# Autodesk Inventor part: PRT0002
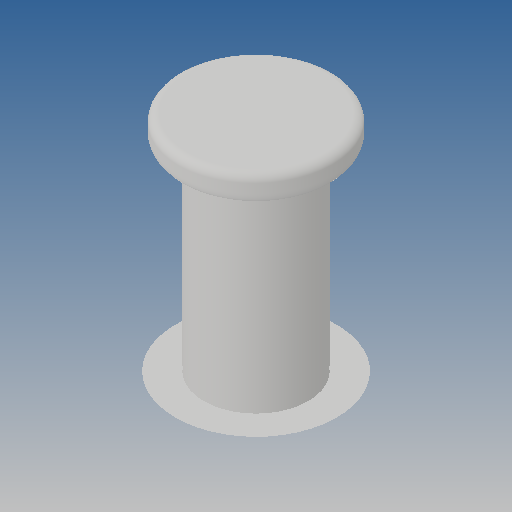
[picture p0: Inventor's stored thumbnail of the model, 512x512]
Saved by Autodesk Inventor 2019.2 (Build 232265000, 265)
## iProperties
Created: 2012-06
Part Number: PRT0002
Material: Ogólny
Document SubType Name: Modeling
Designer: CADENGINEERING4
Density: 1 g/cm^3
Appearance: Domyślna
Author: CADENGINEERING4
Revision Number: 1LAST_VERSION
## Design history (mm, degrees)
feature "Baza1"
node "Bryła1"
